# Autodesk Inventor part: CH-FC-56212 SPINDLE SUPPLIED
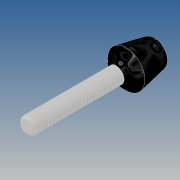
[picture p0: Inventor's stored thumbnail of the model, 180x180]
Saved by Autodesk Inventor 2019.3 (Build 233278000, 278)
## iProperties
Created: 2017-11
Part Number: CH-FC-56212 SPINDLE SUPPLIED
Material: Ogólny
Document SubType Name: Modeling
Designer: Admin
Density: 1 g/cm^3
Appearance: Domyślna
Author: Admin
Revision Number: ÈÎºÎ
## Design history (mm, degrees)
feature "Ðý×ª2"
node "Bryła1"
